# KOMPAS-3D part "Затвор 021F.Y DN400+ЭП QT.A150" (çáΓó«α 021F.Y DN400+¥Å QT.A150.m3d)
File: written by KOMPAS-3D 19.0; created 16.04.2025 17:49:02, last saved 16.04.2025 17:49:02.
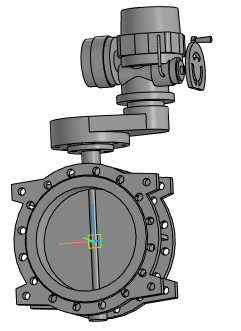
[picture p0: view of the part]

Document properties: Полное имя файла: Затвор 021F.Y DN400+ЭП QT.A150.a3d

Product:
- Part/product: Затвор 021F.Y DN400+ЭП QT.A150
    Масса: 344.131

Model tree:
1. Операция без истории:1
